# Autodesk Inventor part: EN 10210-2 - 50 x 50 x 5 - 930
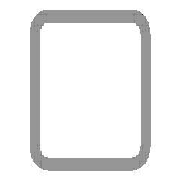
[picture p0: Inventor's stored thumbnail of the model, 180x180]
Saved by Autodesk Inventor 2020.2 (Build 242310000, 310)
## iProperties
IsCustomPart: 1
_CCFamilyMember: 16
_CCFamilyDisplayName: DIN EN 10210-2 (USAS B17.1 quadratisch) - Rohrleitung — In Klammern angegebene Größen wurden aufgehoben
_FrameMemberDoc: Frame Member File
_Version: 15.0.0
_GetPNFromCC: 1
Created: 2019-10
Part Number: EN 10210-2 - 50 x 50 x 5 - 930
Material: Stahl, weich
Description: Rohrleitung
Document SubType Name: Modeling
Standard: DIN
Designer: lutzd
Standard Revision: 2006-07
Standards Organization: DIN
Language: de-DE
Size Designation: 50 x 50 x 5
Categories: <MemberInstance><Categories><Category DisplayName="Profile" InternalName="089c4875-fa83-4c05-b084-43b9cc11f5ed" Mnemonic="GRDR"><CategoryParameter DisplayName="
Stock Number: 50 x 50 x 5
Mass: 6374.61 g
Surface Area: 3165.88 cm^2
Volume: 812.053 cm^3
Density: 7.85 g/cm^3
Appearance: Semi-Polished(8)
G_L: 930,000 mm
G_W: 50,000 mm
G_H: 50,000 mm
Dimensions: 50x50x930 mm
Mass: 6,375 kg
DocNumber: ADSK-014301
Folder: .
+55E898A3-B07A-4120-8C96-5A1DAE010CCB+SCHNITTDETAIL1: Schnittwinkel 90,00 grd
+AAAD6DF0-6248-45B0-AE50-03011BE56521+SCHNITTDETAIL2: Schnittwinkel 90,00 grd
VLT_Material: Stahl, weich
Title: Profil-Bauteil
Author: lutzd
Revision Number: -
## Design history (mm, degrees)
node "Startebene"
node "Endebene"
sketch "Skizze"
  geometry: L1 (-25, -17.5)-(-25, 17.5); L2 (-17.5, 25)-(17.5, 25); L3 (25, 17.5)-(25, -17.5); L4 (17.5, -25)-(-17.5, -25); L5 (-15, 20)-(15, 20); L6 (20, 15)-(20, -15); L7 (15, -20)-(-15, -20); L8 (-20, -15)-(-20, 15); L9 (0, 37.175)-(0, -37.175) reference; L10 (-37.175, 0)-(37.175, 0) reference; A1 r 7.5 centre (-17.5, -17.5) between (-25, -17.5) and (-17.5, -25); A2 r 7.5 centre (-17.5, 17.5) between (-17.5, 25) and (-25, 17.5); A3 r 7.5 centre (17.5, 17.5) between (25, 17.5) and (17.5, 25); A4 r 7.5 centre (17.5, -17.5) between (17.5, -25) and (25, -17.5); A5 r 5 centre (-15, -15) between (-20, -15) and (-15, -20); A6 r 5 centre (-15, 15) between (-15, 20) and (-20, 15); A7 r 5 centre (15, 15) between (20, 15) and (15, 20); A8 r 5 centre (15, -15) between (15, -20) and (20, -15)
  constraints: 16 end point, 16 point on circle, 16 tangent, 8 centre point, 6 equal radius, 4 parallel, 2 perpendicular, 2 other
  dimensions: "d7" = 7.5 radius of A1 (= G_IR); "d10" = 50 distance between parallel lines of L2 L4 (= G_H); "d11" = 50 distance between parallel lines of L1 L3 (= G_W); "d12" = 5 distance between parallel lines of L3 L6 (= G_T); "d15" = 25 distance between parallel lines of L2 L10 (= 0.5 x d10); "d16" = 25 distance between parallel lines of L9 L3 (= 0.5 x d11); "d19" = 5 radius of A5 (= G_T); "d20" = 5 distance between parallel lines of L4 L7 (= G_T)
extrude "Körper" new body sketch "Skizze" stored distance "d3" = 930 (= G_L); taper "d4" = 0 deg
node "Driven Length"
  sketch "Sketch3"
    geometry: L1 (0, 0)-(10, 0) reference
    constraints: 2 end point, 1 horizontal
  workplane "Work Plane3"
  sketch "Sketch4"
    geometry: L1 (-2, 50)-(12, 50) reference; L2 (-2, 980)-(12, 980) reference
    dimensions: "d18" = 930 distance between parallel lines of L1 L2 (derived)
workplane "Arbeitsebene4"
feature "Trennen1"
workplane "Arbeitsebene5"
feature "Trennen2"
body "Solid1"
other parameters: "G_W" = 50 [user parameter; used in 1 equation term], "G_H" = 50 [user parameter; used in 1 equation term], "G_T" = 5 [user parameter; used in 3 equation terms], "G_IR" = 7.5 [user parameter; used in 1 equation term], "G_L" = 930 (= d18) [user parameter; used in 1 equation term], "d17" = 90 deg
